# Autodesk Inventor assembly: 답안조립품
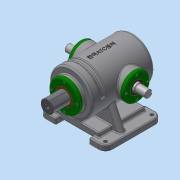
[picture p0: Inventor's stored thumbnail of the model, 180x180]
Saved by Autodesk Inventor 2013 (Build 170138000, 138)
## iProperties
Created: 2018-06
Part Number: 답안조립품
Document SubType Name: Assembly
Designer: Administrator
Author: Administrator
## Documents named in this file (13)
- C:\Users\Administrator\Desktop\380628V1009\답안조립품.iam
- C:\Users\Administrator\Desktop\380628V1009\본체.ipt
- C:\Users\Administrator\Desktop\380628V1009\가변스프링.ipt
- C:\Users\Administrator\Desktop\380628V1009\베어링 6205.ipt
- 베어링 6205.ipt
- C:\Users\Administrator\Desktop\380628V1009\볼트 M4.ipt
- C:\Users\Administrator\Desktop\380628V1009\부시.ipt
- C:\Users\Administrator\Desktop\380628V1009\슬라이드 커버.ipt
- C:\Users\Administrator\Desktop\380628V1009\슬라이드.ipt
- C:\Users\Administrator\Desktop\380628V1009\오일실.ipt
- 오일실.ipt
- C:\Users\Administrator\Desktop\380628V1009\축 커버.ipt
- C:\Users\Administrator\Desktop\380628V1009\편심축.ipt
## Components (1 placed, 1 different names)
1. 가변스프링:1
